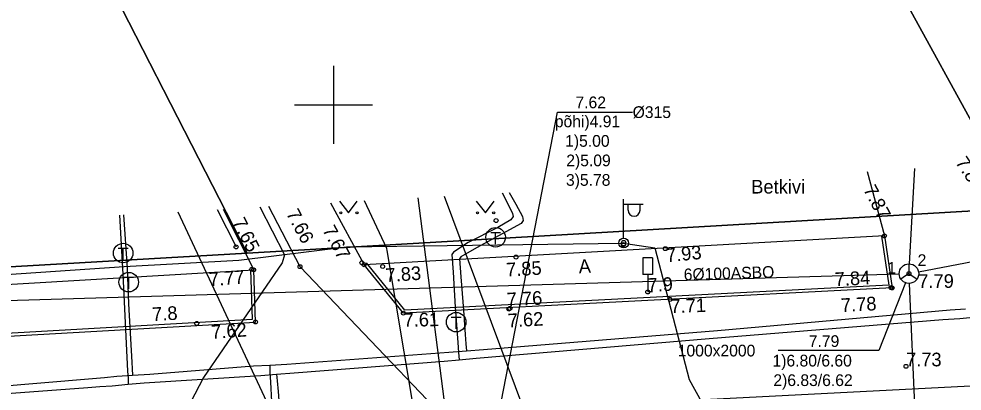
# Model space of a CAD drawing. Extents: x 473307 to 473719, y 6532843 to 6533381.
# Drawn here: x 473533.89 to 473582.18, y 6533285.34 to 6533304.4 of the extents above; entities that cross this region are included whole.
import ezdxf

# ---------------------------------------------------------------- set-up
doc = ezdxf.new("R2010")
doc.units = 0
for name, color, linetype in [('Default', 7, 'Continuous'), ('HALJASTUS', 7, 'Continuous'), ('KORGUS', 7, 'Continuous'), ('KPKAABEL', 7, 'Continuous'), ('KTRASS', 7, 'Continuous'), ('LIIKLUS', 7, 'Continuous'), ('MPKAABEL', 7, 'Continuous'), ('PIIR', 7, 'Continuous'), ('POST', 7, 'Continuous'), ('SIKAEV', 7, 'Continuous'), ('SIKAEV_NR', 7, 'Continuous'), ('SITRASS', 7, 'Continuous'), ('SITRASS_TEKST', 7, 'Continuous'), ('SKKAEV_NR', 7, 'Continuous'), ('SKTRASS', 7, 'Continuous'), ('TEE', 7, 'Continuous'), ('TKAEV', 7, 'Continuous'), ('TTRASS', 7, 'Continuous'), ('VORK', 7, 'Continuous'), ('VTRASS', 7, 'Continuous')]:
    doc.layers.add(name, color=color, linetype=linetype)

# ---------------------------------------------------------------- blocks, each defined once
blk = doc.blocks.new('SIKAEV')
at = {"layer": 'Default'}
for p, q in [((0, 1), (0, 0)), ((0, 0), (-0.83, -0.55)), ((0, 0), (0.83, -0.55))]:
    blk.add_line(p, q, dxfattribs=at)
blk.add_circle((0, 0), 1, dxfattribs=at)
blk = doc.blocks.new('SOKAEV')
at = {"layer": 'Default'}
for p, q in [((-0.5, 0.5), (0.5, 0.5)), ((0, -0.7), (0, 0.5))]:
    blk.add_line(p, q, dxfattribs=at)
blk.add_circle((0, 0), 1, dxfattribs=at)
blk = doc.blocks.new('LIIKLM')
at = {"layer": 'Default'}
for points in [[(-0.5, 3.5), (-0.5, 1.8)], [(0.5, 3.5), (-0.5, 3.5)], [(0.5, 3.5), (0.5, 1.8)], [(0.5, 1.8), (-0.5, 1.8)], [(0, 1.8), (0, 0)], [(0.5, 0), (0, 0)]]:
    blk.add_lwpolyline(points, dxfattribs=at)
blk = doc.blocks.new('MEPOST')
at = {"layer": 'Default'}
blk.add_circle((0, 0), 0.5, dxfattribs=at)
for start, end in [(0, 180), (180, 0)]:
    blk.add_arc((0, 0), 0.25, start, end, dxfattribs=at)
blk = doc.blocks.new('VAPOST')
at = {"layer": 'Default'}
for p, q in [((0, 0.5), (0, 4.5)), ((0, 4), (2, 4)), ((0.453, 3.358), (0.453, 4)), ((1.679, 3.358), (1.679, 4))]:
    blk.add_line(p, q, dxfattribs=at)
blk.add_arc((1.066, 3.358), 0.613, 180, 0, dxfattribs=at)
blk = doc.blocks.new('MURU')
at = {"layer": 'Default'}
for p, q in [((-0.927, 1.213), (0, 0)), ((0, 0), (0.891, 1.213))]:
    blk.add_line(p, q, dxfattribs=at)
for centre in [(-0.802, 0), (0.856, 0)]:
    blk.add_circle(centre, 0.11, dxfattribs=at)
blk = doc.blocks.new('VKORIS')
at = {"layer": 'Default'}
for p, q in [((0, 4), (0, -4)), ((-4, 0), (4, 0))]:
    blk.add_line(p, q, dxfattribs=at)

msp = doc.modelspace()

# ---------------------------------------------------------------- linework, layer by layer
at = {"layer": 'HALJASTUS'}
msp.add_lwpolyline([(473544.038, 6533294.641), (473545.008, 6533292.723)], dxfattribs=at)
at = {"layer": 'KORGUS'}
for centre in [(473558.319, 6533294.072), (473578.203, 6533293.288), (473545.008, 6533292.723), (473564.836, 6533292.842), (473566.986, 6533292.632), (473559.339, 6533292.202), (473548.282, 6533291.71), (473551.448, 6533291.914), (473551.564, 6533291.808), (473552.516, 6533291.719), (473545.818, 6533291.573), (473545.91, 6533291.549), (473579.457, 6533291.354), (473566.086, 6533290.415), (473578.533, 6533290.643), (473578.595, 6533290.622), (473567.233, 6533290.035), (473553.574, 6533289.329), (473558.972, 6533289.536), (473559.026, 6533289.574), (473542.996, 6533288.806), (473546.003, 6533288.876), (473579.306, 6533286.608)]:
    msp.add_circle(centre, 0.1, dxfattribs=at)
at = {"layer": 'KPKAABEL'}
for points in [[(473615.664, 6533298.845), (473618.359, 6533285.308), (473618.229, 6533283.689), (473616.939, 6533282.082), (473615.155, 6533281.15), (473604.958, 6533279.899), (473594.081, 6533279.705), (473584.872, 6533279.168), (473575.551, 6533278.541), (473567.551, 6533277.966), (473562.423, 6533278.215), (473560.662, 6533279.216), (473558.752, 6533280.739), (473548.282, 6533291.71), (473546.684, 6533294.796)], [(473546.224, 6533294.769), (473547.496, 6533292.321), (473547.372, 6533291.903), (473543.34, 6533286.034), (473541.318, 6533282.133), (473539.554, 6533279.533), (473538.159, 6533277.421), (473531.307, 6533275.958), (473516.917, 6533275.473), (473488.292, 6533273.67), (473476.815, 6533273.569), (473476.248, 6533273.293), (473475.851, 6533272.737), (473475.958, 6533272.062), (473476.382, 6533269.243), (473476.692, 6533268.57), (473477.067, 6533268.256), (473477.763, 6533268.245)], [(473591.16, 6533268.89), (473578.283, 6533269.448), (473577.337, 6533269.561), (473576.127, 6533270.011), (473575.73, 6533270.915), (473575.975, 6533272.087), (473576.287, 6533272.863), (473575.638, 6533274.403), (473574.857, 6533275.668), (473573.783, 6533275.999), (473570.307, 6533276.059), (473567.288, 6533276.177), (473564.943, 6533276.268), (473559.603, 6533276.111), (473556.406, 6533275.858), (473555.443, 6533276.028), (473555.021, 6533277.632), (473554.665, 6533279.574), (473554.486, 6533282.168), (473552.745, 6533292.544), (473552.729, 6533292.649), (473551.576, 6533295.083)]]:
    msp.add_lwpolyline(points, dxfattribs=at)
at = {"layer": 'KTRASS'}
msp.add_lwpolyline([(473555.66, 6533295.323), (473563.303, 6533274.813)], dxfattribs=at)
at = {"layer": 'MPKAABEL'}
for points in [[(473542.034, 6533294.523), (473549.77, 6533277.94), (473555.143, 6533270.091), (473555.526, 6533269.435), (473556.291, 6533268.996), (473557.105, 6533268.695), (473558.02, 6533267.83), (473559.509, 6533265.389), (473561.517, 6533248.21)], [(473525.948, 6533290.824), (473539.287, 6533291.718), (473545.145, 6533292.046), (473550.656, 6533292.727), (473564.851, 6533292.918)], [(473525.948, 6533290.824), (473539.287, 6533291.718), (473545.145, 6533292.046), (473550.656, 6533292.727), (473564.851, 6533292.918), (473566.45, 6533292.671), (473568.205, 6533285.94), (473572.537, 6533278.089), (473573.477, 6533277.469), (473574.937, 6533277.378), (473588.904, 6533277.934), (473598.263, 6533278.206), (473600.541, 6533275.557), (473602.095, 6533267.853), (473603.802, 6533258.2), (473603.216, 6533257.059), (473604.096, 6533256.527), (473606.448, 6533242.906), (473608.439, 6533231.57), (473607.954, 6533230.431), (473608.769, 6533229.316), (473610.682, 6533219.295)], [(473564.851, 6533292.918), (473566.45, 6533292.671), (473568.205, 6533285.94), (473572.537, 6533278.089), (473573.477, 6533277.469), (473574.937, 6533277.378), (473588.904, 6533277.934), (473598.263, 6533278.206)]]:
    msp.add_lwpolyline(points, dxfattribs=at)
at = {"layer": 'PIIR'}
for points in [[(473546.848, 6533380.885), (473548.67, 6533377.72), (473552.06, 6533377.52), (473554.47, 6533373.83), (473554.77, 6533368.87), (473546.99, 6533364.16), (473553.35, 6533352.46), (473569.29, 6533323.48), (473585.1, 6533294.7), (473545.58, 6533292.4), (473536.31, 6533310.52), (473520.75, 6533316.46), (473504.35, 6533345.55), (473500.43, 6533353.19), (473502.79, 6533354.42), (473513.31, 6533359.89), (473507.16, 6533371.28), (473506.33, 6533372.83), (473521.647, 6533380.885)], [(473306.698, 6533269.314), (473318.22, 6533273.04), (473319.15, 6533273.32), (473325.84, 6533274.58), (473345.31, 6533277.99), (473387.78, 6533284.78), (473409.45, 6533285.94), (473429.73, 6533289.19), (473430.17, 6533286.8), (473480.73, 6533288.66), (473545.58, 6533292.4), (473585.1, 6533294.7), (473599.09, 6533295.91), (473601.54, 6533272.81), (473586.5, 6533271.93), (473496.37, 6533266.79), (473372.23, 6533259.41), (473356.5, 6533258.46), (473354.97, 6533266.17), (473326.61, 6533261.28), (473306.698, 6533254.866)]]:
    msp.add_lwpolyline(points, dxfattribs=at)
for points in [[(473480.69, 6533288.74), (473471.79, 6533305.18), (473476.25, 6533307.51), (473476.21, 6533307.58), (473461.17, 6533334.49), (473465.17, 6533335.3), (473485.24, 6533339.32), (473504.35, 6533345.55), (473520.75, 6533316.46), (473536.31, 6533310.52), (473545.58, 6533292.4), (473480.73, 6533288.66)], [(473569.29, 6533323.48), (473592.3, 6533328.43), (473599.09, 6533295.91), (473585.1, 6533294.7)]]:
    msp.add_lwpolyline(points, close=True, dxfattribs=at)
at = {"layer": 'SIKAEV_NR'}
msp.add_lwpolyline([(473579.274, 6533290.888), (473577.913, 6533287.415), (473572.758, 6533287.415)], dxfattribs=at)
at = {"layer": 'SITRASS'}
msp.add_line((473580.67, 6533264.582), (473579.479, 6533290.854), dxfattribs=at)
for points in [[(473579.484, 6533291.853), (473579.75, 6533296.737)], [(473579.948, 6533291.448), (473598.48, 6533295.005)], [(473530.957, 6533289.903), (473578.957, 6533291.339)]]:
    msp.add_lwpolyline(points, dxfattribs=at)
at = {"layer": 'SKKAEV_NR'}
msp.add_lwpolyline([(473558.593, 6533284.865), (473561.457, 6533299.625), (473565.312, 6533299.625)], dxfattribs=at)
at = {"layer": 'SKTRASS'}
msp.add_lwpolyline([(473558.997, 6533284.4), (473592.599, 6533286.129)], dxfattribs=at)
at = {"layer": 'TEE'}
for points in [[(473577.318, 6533296.594), (473578.203, 6533293.288)], [(473549.844, 6533294.982), (473551.564, 6533291.808)], [(473544.346, 6533294.659), (473545.91, 6533291.549)], [(473578.203, 6533293.288), (473551.564, 6533291.808)], [(473578.203, 6533293.288), (473578.595, 6533290.622), (473553.574, 6533289.329), (473551.564, 6533291.808)], [(473578.054, 6533293.266), (473578.422, 6533290.763), (473553.642, 6533289.483), (473551.681, 6533291.902)], [(473484.319, 6533288.04), (473498.094, 6533288.724), (473545.91, 6533291.549)], [(473484.333, 6533287.708), (473485.767, 6533285.452), (473546.003, 6533288.876), (473545.91, 6533291.549)], [(473484.46, 6533287.788), (473485.846, 6533285.607), (473545.848, 6533289.017), (473545.76, 6533291.543)]]:
    msp.add_lwpolyline(points, dxfattribs=at)
at = {"layer": 'TTRASS'}
for points in [[(473558.632, 6533295.497), (473558.808, 6533295.163), (473559.168, 6533294.429), (473559.187, 6533294.283), (473559.082, 6533294.11), (473558.414, 6533293.718), (473556.887, 6533292.957), (473556.14, 6533292.453), (473556.062, 6533292.343), (473556.117, 6533291.433), (473556.224, 6533289.63), (473556.37, 6533287.835), (473556.402, 6533287.319), (473556.429, 6533286.944)], [(473558.991, 6533295.518), (473559.324, 6533294.906), (473559.671, 6533294.273), (473559.7, 6533294.068), (473559.608, 6533293.915), (473557.312, 6533292.677), (473556.517, 6533292.222), (473556.443, 6533292.117), (473556.514, 6533291.195), (473556.645, 6533289.492), (473556.74, 6533288.241), (473556.777, 6533287.752), (473556.812, 6533287.398)], [(473539.046, 6533294.348), (473539.114, 6533293.141), (473539.203, 6533291.333), (473539.455, 6533286.363), (473539.491, 6533286.005), (473539.49, 6533285.693)], [(473539.254, 6533294.36), (473539.43, 6533291.641), (473539.507, 6533289.812), (473539.677, 6533286.822), (473539.684, 6533286.475), (473539.699, 6533286.147)], [(473530.121, 6533285.357), (473537.652, 6533285.985), (473538.281, 6533286.042), (473538.909, 6533286.098), (473539.699, 6533286.147), (473540.599, 6533286.203), (473545.897, 6533286.63), (473546.73, 6533286.674), (473547.603, 6533286.721), (473555.905, 6533287.331), (473556.812, 6533287.398), (473557.673, 6533287.469), (473569.649, 6533288.435), (473581.571, 6533289.506), (473582.357, 6533289.56)], [(473529.805, 6533284.958), (473537.412, 6533285.531), (473538.041, 6533285.574), (473538.669, 6533285.617), (473539.49, 6533285.693), (473540.304, 6533285.768), (473546.276, 6533286.136), (473547.077, 6533286.201), (473547.984, 6533286.274), (473555.655, 6533286.865), (473556.429, 6533286.944), (473557.304, 6533287.033), (473569.224, 6533288.034), (473581.194, 6533289.011), (473582.064, 6533289.054), (473583.759, 6533289.232)], [(473546.73, 6533286.674), (473546.743, 6533286.322), (473546.763, 6533285.79), (473546.825, 6533284.8), (473546.92, 6533283.591), (473546.998, 6533282.657), (473547.424, 6533277.599), (473547.489, 6533276.819), (473547.65, 6533276.703), (473548.42, 6533276.779), (473552.171, 6533277.246), (473553.047, 6533277.344), (473553.18, 6533277.259), (473553.245, 6533276.371), (473553.82, 6533270.399), (473553.929, 6533269.272)], [(473547.077, 6533286.201), (473547.112, 6533285.86), (473547.157, 6533285.321), (473547.229, 6533284.389), (473547.253, 6533284.092), (473547.328, 6533283.178), (473547.734, 6533278.192), (473547.802, 6533277.362), (473547.925, 6533277.228), (473548.77, 6533277.287), (473552.437, 6533277.651), (473553.278, 6533277.705), (473553.432, 6533277.596), (473553.475, 6533276.686), (473554.126, 6533270.721), (473554.282, 6533269.289)]]:
    msp.add_lwpolyline(points, dxfattribs=at)
at = {"layer": 'VTRASS'}
msp.add_lwpolyline([(473554.316, 6533295.244), (473556.042, 6533281.885)], dxfattribs=at)

# ---------------------------------------------------------------- block references
at = {"layer": 'HALJASTUS', "xscale": 0.5, "yscale": 0.5}
for p in [(473550.771, 6533294.467), (473557.771, 6533294.467)]:
    msp.add_blockref('MURU', p, dxfattribs=at)
at = {"layer": 'LIIKLUS', "xscale": 0.5, "yscale": 0.5}
msp.add_blockref('LIIKLM', (473566.086, 6533290.415), dxfattribs=at)
at = {"layer": 'POST', "xscale": 0.5, "yscale": 0.5}
for name in ['VAPOST', 'MEPOST']:
    msp.add_blockref(name, (473564.851, 6533292.918), dxfattribs=at)
at = {"layer": 'SIKAEV', "xscale": 0.5, "yscale": 0.5}
msp.add_blockref('SIKAEV', (473579.457, 6533291.354), dxfattribs=at)
at = {"layer": 'TKAEV', "xscale": 0.5, "yscale": 0.5}
for p in [(473558.296, 6533293.219), (473539.227, 6533292.408), (473539.514, 6533290.919), (473556.277, 6533288.873)]:
    msp.add_blockref('SOKAEV', p, dxfattribs=at)
at = {"layer": 'VORK', "xscale": 0.5, "yscale": 0.5}
msp.add_blockref('VKORIS', (473550, 6533300), dxfattribs=at)

# ---------------------------------------------------------------- texts
at = {"layer": 'KORGUS'}
for s, rotation, p in [('7.89', 303.8575, (473581.809, 6533297.049)), ('7.87', 297.6744, (473577.1, 6533295.664)), ('7.66', 297.9939, (473547.555, 6533294.435)), ('7.65', 297.2631, (473544.798, 6533294.001)), ('7.67', 298.4593, (473549.412, 6533293.592)), ('7.93', 5.5949, (473567.054, 6533291.935)), ('7.85', 3.2949, (473558.85, 6533291.203)), ('7.77', 4.1775, (473543.642, 6533290.712)), ('7.83', 3.9364, (473552.687, 6533290.92)), ('7.84', 3.1677, (473575.672, 6533290.71)), ('7.9', 2.9578, (473566.086, 6533290.415)), ('7.76', 3.1677, (473558.882, 6533289.671)), ('7.71', 1.8937, (473567.256, 6533289.335)), ('7.78', 3.1677, (473575.992, 6533289.384)), ('7.8', 3.297, (473540.73, 6533288.922)), ('7.61', 1.3081, (473553.59, 6533288.629)), ('7.62', 3.1677, (473558.936, 6533288.599)), ('7.62', 4.2034, (473543.76, 6533288.009))]:
    msp.add_text(s, height=0.7, rotation=rotation, dxfattribs=at).set_placement(p)
for s, p in [('7.79', (473579.932, 6533290.625)), ('7.73', (473579.306, 6533286.608))]:
    msp.add_text(s, height=0.7, dxfattribs=at).set_placement(p)
at = {"layer": 'SIKAEV_NR'}
for s, p in [('2', (473579.9, 6533291.746)), ('1', (473578.358, 6533291.354)), ('7.79', (473574.33, 6533287.599)), ('1000x2000', (473567.62, 6533287.115)), ('1)6.80/6.60', (473572.473, 6533286.599)), ('2)6.83/6.62', (473572.516, 6533285.599))]:
    msp.add_text(s, height=0.6, dxfattribs=at).set_placement(p)
at = {"layer": 'SITRASS_TEKST'}
msp.add_text('6%%c100ASBO', height=0.6, rotation=1.7135, dxfattribs=at).set_placement((473567.935, 6533291.009))
at = {"layer": 'SKKAEV_NR'}
for s, p in [('7.62', (473562.384, 6533299.825)), ('%%C315', (473565.312, 6533299.325)), ('põhi)4.91', (473561.327, 6533298.853)), ('1)5.00', (473561.856, 6533297.853)), ('2)5.09', (473561.913, 6533296.853)), ('3)5.78', (473561.899, 6533295.853))]:
    msp.add_text(s, height=0.6, dxfattribs=at).set_placement(p)
at = {"layer": 'TEE'}
msp.add_text('Betkivi', height=0.7, dxfattribs=at).set_placement((473571.382, 6533295.458))
msp.add_text('A', height=0.7, rotation=2.9578, dxfattribs=at).set_placement((473562.564, 6533291.37))

doc.saveas('drawing.dxf')
